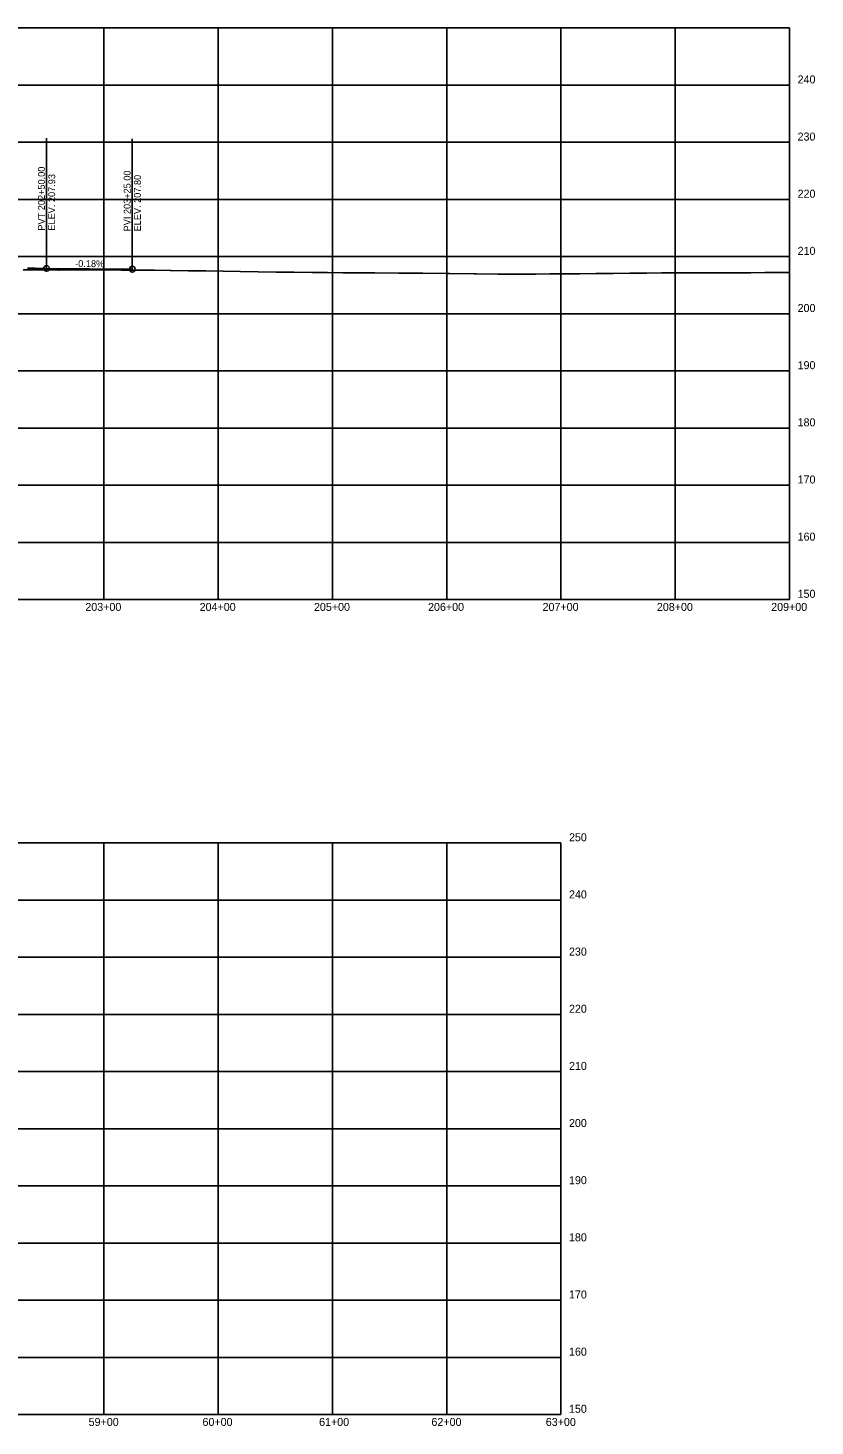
# Model space of a CAD drawing. Extents: x 1138442 to 1165793, y 1654070 to 1657687.
# Drawn here: x 1149139 to 1149828, y 1655043 to 1656266 of the extents above; entities that cross this region are included whole.
import ezdxf

# ---------------------------------------------------------------- set-up
doc = ezdxf.new("R2010")
doc.units = 0
for name, color, linetype in [('B_Dimensions', 7, 'Continuous'), ('R_Axis', 7, 'Continuous'), ('R_Axis Annot', 7, 'Continuous'), ('R_Grid', 7, 'Continuous'), ('R_Proposed Const Limits_Hand', 7, 'Continuous'), ('R_Vert Alg Annot', 7, 'Continuous')]:
    doc.layers.add(name, color=color, linetype=linetype)

msp = doc.modelspace()

# ---------------------------------------------------------------- linework, layer by layer
at = {"layer": 'B_Dimensions'}
msp.add_line((1149155.7, 1656056.1), (1149230.7, 1656055.4), dxfattribs=at)
msp.add_lwpolyline([(1149139, 1656056.2), (1149141.1, 1656056.2), (1149143.2, 1656056.2), (1149145.3, 1656056.2), (1149147.4, 1656056.1), (1149149.5, 1656056.1), (1149151.5, 1656056.1), (1149153.6, 1656056.1), (1149155.7, 1656056.1)], dxfattribs=at)
at = {"layer": 'R_Axis'}
for p, q in [((1149805.7, 1655766.4), (1149805.7, 1656266.4)), ((1148105.7, 1655766.4), (1149805.7, 1655766.4)), ((1149605.7, 1655053.4), (1149605.7, 1655553.4)), ((1148105.7, 1655053.4), (1149605.7, 1655053.4))]:
    msp.add_line(p, q, dxfattribs=at)
at = {"layer": 'R_Grid'}
for p, q in [((1148105.7, 1656266.4), (1149805.7, 1656266.4)), ((1148105.7, 1656266.4), (1149805.7, 1656266.4)), ((1149205.7, 1655766.4), (1149205.7, 1656266.4)), ((1149305.7, 1655766.4), (1149305.7, 1656266.4)), ((1149405.7, 1655766.4), (1149405.7, 1656266.4)), ((1149505.7, 1655766.4), (1149505.7, 1656266.4)), ((1149605.7, 1655766.4), (1149605.7, 1656266.4)), ((1149705.7, 1655766.4), (1149705.7, 1656266.4)), ((1148105.7, 1656216.4), (1149805.7, 1656216.4)), ((1148105.7, 1656166.4), (1149805.7, 1656166.4)), ((1148105.7, 1656116.4), (1149805.7, 1656116.4)), ((1148105.7, 1656066.4), (1149805.7, 1656066.4)), ((1148105.7, 1656016.4), (1149805.7, 1656016.4)), ((1148105.7, 1655966.4), (1149805.7, 1655966.4)), ((1148105.7, 1655916.4), (1149805.7, 1655916.4)), ((1148105.7, 1655866.4), (1149805.7, 1655866.4)), ((1148105.7, 1655816.4), (1149805.7, 1655816.4)), ((1148105.7, 1655553.4), (1149605.7, 1655553.4)), ((1148105.7, 1655553.4), (1149605.7, 1655553.4)), ((1149205.7, 1655053.4), (1149205.7, 1655553.4)), ((1149305.7, 1655053.4), (1149305.7, 1655553.4)), ((1149405.7, 1655053.4), (1149405.7, 1655553.4)), ((1149505.7, 1655053.4), (1149505.7, 1655553.4)), ((1148105.7, 1655503.4), (1149605.7, 1655503.4)), ((1148105.7, 1655453.4), (1149605.7, 1655453.4)), ((1148105.7, 1655403.4), (1149605.7, 1655403.4)), ((1148105.7, 1655353.4), (1149605.7, 1655353.4)), ((1148105.7, 1655303.4), (1149605.7, 1655303.4)), ((1148105.7, 1655253.4), (1149605.7, 1655253.4)), ((1148105.7, 1655203.4), (1149605.7, 1655203.4)), ((1148105.7, 1655153.4), (1149605.7, 1655153.4)), ((1148105.7, 1655103.4), (1149605.7, 1655103.4))]:
    msp.add_line(p, q, dxfattribs=at)
at = {"layer": 'R_Proposed Const Limits_Hand'}
msp.add_lwpolyline([(1149135.1, 1656054.9), (1149150.4, 1656054.8), (1149151, 1656054.8), (1149166.1, 1656054.6), (1149167, 1656054.6), (1149186.1, 1656054.7), (1149187.2, 1656054.7), (1149206.3, 1656054.8), (1149207.4, 1656054.8), (1149220.9, 1656054.7), (1149221.6, 1656054.6), (1149235.3, 1656054.5), (1149235.9, 1656054.5), (1149249.6, 1656054.4), (1149250.1, 1656054.4), (1149263.9, 1656054.3), (1149264.3, 1656054.3), (1149264.8, 1656054.3), (1149279.5, 1656054), (1149279.9, 1656054), (1149294.7, 1656053.8), (1149295, 1656053.8), (1149309.8, 1656053.6), (1149310.1, 1656053.6), (1149325, 1656053.3), (1149325.2, 1656053.3), (1149340.7, 1656053.1), (1149340.8, 1656053.1), (1149356.4, 1656052.9), (1149356.5, 1656052.9), (1149362.7, 1656052.8), (1149372.1, 1656052.7), (1149372.2, 1656052.7), (1149387.9, 1656052.4), (1149388, 1656052.4), (1149400.5, 1656052.4), (1149401.4, 1656052.4), (1149401.4, 1656052.4), (1149415, 1656052.3), (1149415.1, 1656052.3), (1149428.5, 1656052.2), (1149428.8, 1656052.2), (1149442.1, 1656052.1), (1149442.8, 1656052.1), (1149463.5, 1656052), (1149484.2, 1656051.9), (1149484.8, 1656051.9), (1149506.3, 1656051.6), (1149507.4, 1656051.6), (1149508.5, 1656051.6), (1149529.9, 1656051.3), (1149531.5, 1656051.3), (1149550.4, 1656051.1), (1149570.3, 1656050.9), (1149570.7, 1656050.9), (1149583.2, 1656051), (1149583.6, 1656051), (1149595.9, 1656051.2), (1149596.5, 1656051.2), (1149608.6, 1656051.3), (1149609.3, 1656051.3), (1149621.3, 1656051.4), (1149622.2, 1656051.4), (1149636.1, 1656051.6), (1149636.9, 1656051.6), (1149651, 1656051.7), (1149651.6, 1656051.7), (1149665.9, 1656051.9), (1149666.2, 1656051.9), (1149680.8, 1656052), (1149680.9, 1656052), (1149693.5, 1656052.1), (1149698.1, 1656052.1), (1149698.2, 1656052.1), (1149715.4, 1656052.2), (1149715.6, 1656052.2), (1149729.4, 1656052.2), (1149729.7, 1656052.2), (1149743.5, 1656052.3), (1149743.8, 1656052.3), (1149757.6, 1656052.3), (1149757.9, 1656052.3), (1149771.7, 1656052.3), (1149784, 1656052.4), (1149784.6, 1656052.4), (1149796.9, 1656052.4), (1149805.7, 1656052.5)], dxfattribs=at)
at = {"layer": 'R_Vert Alg Annot'}
for p, q in [((1149155.7, 1656086.1), (1149155.7, 1656170.1)), ((1149230.7, 1656085.4), (1149230.7, 1656169.4)), ((1149155.7, 1656056.1), (1149155.7, 1656086.1)), ((1149230.7, 1656055.4), (1149230.7, 1656085.4))]:
    msp.add_line(p, q, dxfattribs=at)
for centre in [(1149155.7, 1656056.1), (1149230.7, 1656055.4)]:
    msp.add_circle(centre, 2.5, dxfattribs=at)

# ---------------------------------------------------------------- texts
at = {"layer": 'R_Axis Annot'}
for s, p in [('240', (1149812.7, 1656217.9)), ('230', (1149812.7, 1656167.9)), ('220', (1149812.7, 1656117.9)), ('210', (1149812.7, 1656067.9)), ('200', (1149812.7, 1656017.9)), ('190', (1149812.7, 1655967.9)), ('180', (1149812.7, 1655917.9)), ('170', (1149812.7, 1655867.9)), ('160', (1149812.7, 1655817.9)), ('150', (1149812.7, 1655767.9)), ('203+00', (1149189.6, 1655756.4)), ('204+00', (1149289.6, 1655756.4)), ('205+00', (1149389.6, 1655756.4)), ('206+00', (1149489.4, 1655756.4)), ('207+00', (1149589.6, 1655756.4)), ('208+00', (1149689.6, 1655756.4)), ('209+00', (1149789.6, 1655756.4)), ('250', (1149612.7, 1655554.9)), ('250', (1149612.7, 1655554.9)), ('240', (1149612.7, 1655504.9)), ('230', (1149612.7, 1655454.9)), ('220', (1149612.7, 1655404.9)), ('210', (1149612.7, 1655354.9)), ('200', (1149612.7, 1655304.9)), ('190', (1149612.7, 1655254.9)), ('180', (1149612.7, 1655204.9)), ('170', (1149612.7, 1655154.9)), ('160', (1149612.7, 1655104.9)), ('150', (1149612.7, 1655054.9)), ('59+00', (1149192.5, 1655043.4)), ('60+00', (1149292.1, 1655043.4)), ('61+00', (1149394.1, 1655043.4)), ('62+00', (1149492.4, 1655043.4)), ('63+00', (1149592.4, 1655043.4))]:
    msp.add_text(s, height=7, dxfattribs=at).set_placement(p)
at = {"layer": 'R_Vert Alg Annot'}
for s, rotation, p in [('PVT 202+50.00', 90, (1149154.2, 1656089.1)), ('ELEV. 207.93', 90, (1149163.2, 1656089.1)), ('PVI 203+25.00', 90, (1149229.2, 1656088.4)), ('ELEV. 207.80', 90, (1149238.2, 1656088.4)), ('-0.18%', 359.4966, (1149180.7, 1656057.3))]:
    msp.add_text(s, height=6, rotation=rotation, dxfattribs=at).set_placement(p)

doc.saveas('drawing.dxf')
